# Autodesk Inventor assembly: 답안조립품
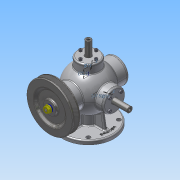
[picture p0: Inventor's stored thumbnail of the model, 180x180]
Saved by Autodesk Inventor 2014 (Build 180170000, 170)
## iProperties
Created: 2016-01
Part Number: 답안조립품
Document SubType Name: Assembly
Designer: Administrator
Mass: 3770.67 g
Surface Area: 2411.02 cm^2
Volume: 903.658 cm^3
Density: 4.17267 g/cm^3
Author: Administrator
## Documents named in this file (17)
- C:\Users\Administrator\Desktop\360108V1013\답안조립품.iam
- C:\Users\Administrator\Desktop\360108V1013\본체.ipt
- C:\Users\Administrator\Desktop\360108V1013\본체커버.ipt
- C:\Users\Administrator\Desktop\360108V1013\베어링- 6202.ipt
- C:\Users\Administrator\Desktop\360108V1013\앞커버.ipt
- C:\Users\Administrator\Desktop\360108V1013\뒤커버.ipt
- C:\Users\Administrator\Desktop\360108V1013\슬라이드 커버.ipt
- C:\Users\Administrator\Desktop\360108V1013\축.ipt
- C:\Users\Administrator\Desktop\360108V1013\오일실.ipt
- C:\Users\Administrator\Desktop\360108V1013\키-4x4.ipt
- C:\Users\Administrator\Desktop\360108V1013\V-벨트풀리.ipt
- C:\Users\Administrator\Desktop\360108V1013\와셔 8x17.ipt
- C:\Users\Administrator\Desktop\360108V1013\너트-M8x1.ipt
- C:\Users\Administrator\Desktop\360108V1013\볼트 M4x0.7.ipt
- C:\Users\Administrator\Desktop\360108V1013\슬라이드.ipt
- C:\Users\Administrator\Desktop\360108V1013\스프링1.ipt
- C:\Users\Administrator\Desktop\360108V1013\스프링2.ipt
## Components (18 placed, 2 different names)
1. V-벨트풀리:1 — 각도:2
2. M4x0.7x12:17
3. M4x0.7x12:1
4. M4x0.7x12:5
5. M4x0.7x12:6
6. M4x0.7x12:7
7. M4x0.7x12:4
8. M4x0.7x12:8
9. M4x0.7x12:9
10. M4x0.7x12:10
11. M4x0.7x12:2
12. M4x0.7x12:11
13. M4x0.7x12:12
14. M4x0.7x12:13
15. M4x0.7x12:3
16. M4x0.7x12:14
17. M4x0.7x12:15
18. M4x0.7x12:16
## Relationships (1: Angle 1)
- 각도:2 [Angle]: V-벨트풀리:1
